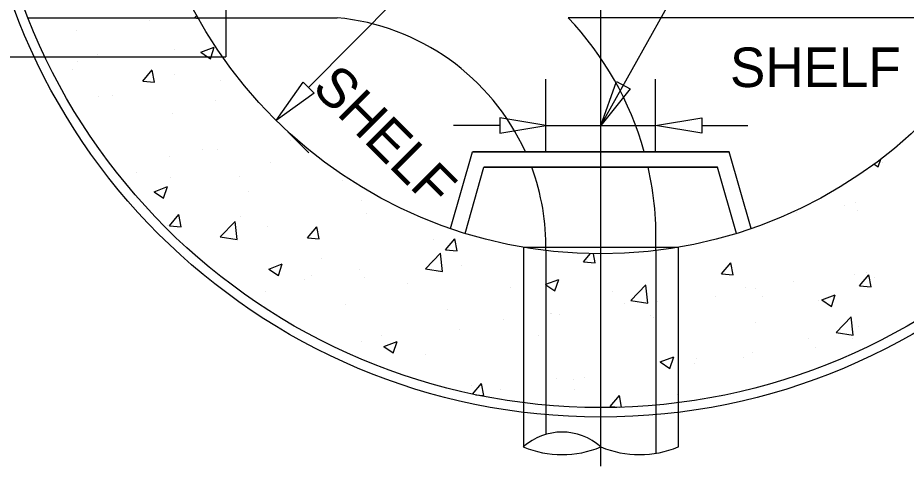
# Model space of a CAD drawing. Extents: x 6712067 to 6713867, y 1867712 to 1869162.
# Drawn here: x 6712906.2 to 6713040.8, y 1867921.4 to 1867989.4 of the extents above; entities that cross this region are included whole.
import ezdxf

# ---------------------------------------------------------------- set-up
doc = ezdxf.new("R2010")
doc.units = 0
for name, color, linetype in [('G-MARK', 7, 'Continuous'), ('G-TEXT', 7, 'Continuous'), ('Misc CnstDet(22)', 7, 'Continuous')]:
    doc.layers.add(name, color=color, linetype=linetype)

msp = doc.modelspace()

# ---------------------------------------------------------------- linework, layer by layer
at = {"layer": 'G-MARK'}
for p, q in [((6713038.81, 1868068.39), (6712950.27, 1867978.84)), ((6712979.24, 1867973.11), (6712972.24, 1867973.11)), ((6712986.22, 1867973.11), (6713002.85, 1867973.11)), ((6713009.84, 1867973.11), (6713016.84, 1867973.11))]:
    msp.add_line(p, q, dxfattribs=at)
at = {"layer": 'G-TEXT'}
for points in [[(6712949.44, 1867979.65), (6712951.11, 1867978.01), (6712945.36, 1867973.86)], [(6712998.97, 1867978.64), (6712994.54, 1867973.11), (6712996.93, 1867979.78)], [(6712979.24, 1867974.27), (6712979.24, 1867971.94), (6712986.22, 1867973.11)], [(6713009.84, 1867974.27), (6713009.84, 1867971.94), (6713002.85, 1867973.11)]]:
    msp.add_lwpolyline(points, close=True, dxfattribs=at)
at = {"layer": 'Misc CnstDet(22)'}
for p, q in [((6712994.54, 1867921.43), (6712994.54, 1868124.34)), ((6712937.71, 1868003.49), (6712937.71, 1867983.53)), ((6712907.75, 1867989.43), (6712933.49, 1867989.43)), ((6712933, 1867989.42), (6712933.01, 1867989.43)), ((6712933, 1867989.42), (6712933.55, 1867989.34)), ((6712933.01, 1867989.43), (6712933.32, 1867989.75)), ((6712933.49, 1867989.43), (6712954.61, 1867989.43)), ((6713055.59, 1867989.43), (6712989.59, 1867989.43)), ((6712926.17, 1867989), (6712926.17, 1867989)), ((6712915.13, 1867987.56), (6712915.13, 1867987.56)), ((6712918.35, 1867983.93), (6712918.35, 1867983.93)), ((6712930.02, 1867984.63), (6712930.02, 1867984.63)), ((6712933.94, 1867984.19), (6712935.99, 1867984.98)), ((6712933.94, 1867984.19), (6712934.93, 1867983.53)), ((6712935.49, 1867983.53), (6712935.99, 1867984.98)), ((6712880.72, 1867983.53), (6712908.71, 1867983.53)), ((6712908.71, 1867983.53), (6712937.71, 1867983.53)), ((6712915.29, 1867982.76), (6712915.29, 1867982.76)), ((6712934.93, 1867983.53), (6712935.39, 1867983.22)), ((6712935.39, 1867983.22), (6712935.49, 1867983.53)), ((6712914.46, 1867981.51), (6712914.46, 1867981.51)), ((6712925.16, 1867979.83), (6712926.57, 1867981.51)), ((6712926.91, 1867979.67), (6712926.56, 1867981.5)), ((6712930.02, 1867980.86), (6712930.02, 1867980.86)), ((6712936.91, 1867979.94), (6712936.91, 1867979.94)), ((6712986.22, 1867969.22), (6712986.22, 1867980.1)), ((6713002.85, 1867969.22), (6713002.85, 1867980.1)), ((6712925.16, 1867979.83), (6712926.91, 1867979.67)), ((6712918.5, 1867977.52), (6712918.5, 1867977.52)), ((6712920.61, 1867977.6), (6712920.61, 1867977.6)), ((6712936.17, 1867976.94), (6712936.17, 1867976.94)), ((6712929.67, 1867974.92), (6712929.67, 1867974.92)), ((6712945.36, 1867973.86), (6712945.36, 1867973.86)), ((6712945.36, 1867973.86), (6712945.36, 1867973.86)), ((6712947.1, 1867972.14), (6712950.33, 1867968.93)), ((6713002.85, 1867973.11), (6713002.85, 1867973.11)), ((6712947.58, 1867970.85), (6712947.58, 1867970.85)), ((6712934.14, 1867969.46), (6712934.14, 1867969.46)), ((6712936.54, 1867969.4), (6712936.54, 1867969.4)), ((6712929.24, 1867968.44), (6712929.24, 1867968.44)), ((6712971.76, 1867957.47), (6712975.08, 1867969.09)), ((6712971.76, 1867957.47), (6712975.08, 1867969.09)), ((6712975.08, 1867969.09), (6713014, 1867969.09)), ((6713014, 1867969.09), (6712975.08, 1867969.09)), ((6713017.33, 1867957.47), (6713014, 1867969.09)), ((6713017.33, 1867957.47), (6713014, 1867969.09)), ((6713036.57, 1867966.81), (6713036.96, 1867967.98)), ((6712944.45, 1867967.41), (6712944.45, 1867967.41)), ((6712973.98, 1867956.74), (6712976.84, 1867966.76)), ((6712973.98, 1867956.74), (6712976.84, 1867966.76)), ((6712976.84, 1867966.76), (6713012.24, 1867966.76)), ((6713012.24, 1867966.76), (6712976.84, 1867966.76)), ((6712986.22, 1867966.77), (6712986.22, 1867966.77)), ((6713002.85, 1867966.77), (6713002.85, 1867966.77)), ((6713015.1, 1867956.74), (6713012.24, 1867966.76)), ((6713015.1, 1867956.74), (6713012.24, 1867966.76)), ((6713035.95, 1867967.22), (6713036.57, 1867966.81)), ((6713037.25, 1867967.45), (6713037.25, 1867967.45)), ((6712924.22, 1867966.04), (6712924.22, 1867966.04)), ((6712929.32, 1867965.22), (6712929.32, 1867965.22)), ((6712939.78, 1867965.39), (6712939.78, 1867965.39)), ((6712926.85, 1867963.06), (6712928.89, 1867963.84)), ((6712928.3, 1867962.08), (6712928.89, 1867963.84)), ((6712955.35, 1867964.72), (6712955.35, 1867964.72)), ((6712926.85, 1867963.06), (6712928.3, 1867962.08)), ((6712941.13, 1867963.06), (6712941.13, 1867963.06)), ((6712958.32, 1867961.78), (6712958.32, 1867961.78)), ((6713033.14, 1867961.44), (6713033.14, 1867961.44)), ((6712959.06, 1867959.75), (6712959.06, 1867959.75)), ((6713024.14, 1867959.96), (6713024.14, 1867959.96)), ((6713031.44, 1867960.92), (6713031.44, 1867960.92)), ((6713033.4, 1867960.21), (6713033.4, 1867960.21)), ((6712929.21, 1867957.9), (6712930.61, 1867959.58)), ((6712930.95, 1867957.75), (6712930.61, 1867959.58)), ((6712936.87, 1867956.19), (6712939.14, 1867958.56)), ((6712939.46, 1867955.79), (6712939.14, 1867958.56)), ((6712939.91, 1867959.35), (6712939.91, 1867959.35)), ((6712928.87, 1867957.9), (6712928.87, 1867957.9)), ((6712929.21, 1867957.9), (6712930.95, 1867957.75)), ((6712944.1, 1867957.71), (6712944.1, 1867957.71)), ((6712950.11, 1867956.08), (6712951.52, 1867957.75)), ((6712951.86, 1867955.92), (6712951.52, 1867957.75)), ((6712936.87, 1867956.19), (6712939.46, 1867955.79)), ((6712950.11, 1867956.08), (6712951.86, 1867955.93)), ((6712969.25, 1867955.78), (6712969.25, 1867955.78)), ((6712971.02, 1867954.24), (6712972.43, 1867955.92)), ((6712972.77, 1867954.09), (6712972.43, 1867955.92)), ((6712982.81, 1867954.64), (6712982.81, 1867924.35)), ((6712982.81, 1867954.64), (6713006.28, 1867954.64)), ((6713006.28, 1867954.64), (6713006.28, 1867924.35)), ((6712967.98, 1867951.37), (6712970.25, 1867953.74)), ((6712970.57, 1867950.97), (6712970.24, 1867953.74)), ((6712971.02, 1867954.24), (6712972.77, 1867954.09)), ((6712986.23, 1867954.14), (6712986.23, 1867926.26)), ((6712991.93, 1867952.42), (6712992.97, 1867953.67)), ((6712993.67, 1867952.27), (6712993.41, 1867953.66)), ((6713002.86, 1867954.14), (6713002.86, 1867923.38)), ((6712944.25, 1867951.32), (6712946.29, 1867952.11)), ((6712945.69, 1867950.34), (6712946.29, 1867952.1)), ((6712952.26, 1867952.87), (6712952.26, 1867952.87)), ((6712968.99, 1867952.69), (6712968.99, 1867952.69)), ((6712973.43, 1867951.92), (6712973.43, 1867951.92)), ((6712991.93, 1867952.42), (6712993.67, 1867952.27)), ((6713012.84, 1867950.59), (6713014.24, 1867952.27)), ((6713014.58, 1867950.43), (6713014.24, 1867952.26)), ((6712944.25, 1867951.32), (6712945.69, 1867950.34)), ((6712950.65, 1867950.28), (6712950.65, 1867950.28)), ((6712957.95, 1867951.25), (6712957.95, 1867951.25)), ((6712967.98, 1867951.37), (6712970.57, 1867950.97)), ((6713012.84, 1867950.59), (6713014.58, 1867950.43)), ((6713033.05, 1867950.5), (6713033.05, 1867950.5)), ((6713033.75, 1867948.76), (6713035.15, 1867950.43)), ((6713034.82, 1867950.88), (6713034.82, 1867950.88)), ((6713035.48, 1867948.61), (6713035.15, 1867950.43)), ((6712949.66, 1867949.82), (6712949.66, 1867949.82)), ((6712958.71, 1867950.05), (6712958.71, 1867950.05)), ((6712965.23, 1867949.17), (6712965.23, 1867949.17)), ((6712986.14, 1867948.99), (6712986.23, 1867949.02)), ((6712986.14, 1867948.99), (6712986.23, 1867948.93)), ((6712986.23, 1867949.02), (6712988.18, 1867949.77)), ((6712986.23, 1867948.93), (6712987.59, 1867948.01)), ((6712987.59, 1867948.01), (6712988.18, 1867949.77)), ((6712999.09, 1867946.54), (6713001.35, 1867948.92)), ((6713023.78, 1867949.42), (6713023.78, 1867949.42)), ((6713036.06, 1867950.05), (6713036.06, 1867950.05)), ((6712943.74, 1867948), (6712943.74, 1867948)), ((6712980.79, 1867948.52), (6712980.79, 1867948.52)), ((6712996.35, 1867947.86), (6712996.35, 1867947.86)), ((6713001.67, 1867946.14), (6713001.35, 1867948.91)), ((6713016.48, 1867948.46), (6713016.48, 1867948.46)), ((6713017.91, 1867948.32), (6713017.91, 1867948.32)), ((6713033.75, 1867948.76), (6713035.49, 1867948.61)), ((6712999.09, 1867946.54), (6713001.67, 1867946.14)), ((6713003.19, 1867946.45), (6713003.19, 1867946.45)), ((6713011.91, 1867947.2), (6713011.91, 1867947.2)), ((6713019.05, 1867947.14), (6713019.05, 1867947.14)), ((6713027.47, 1867946.54), (6713027.47, 1867946.54)), ((6713028.03, 1867946.66), (6713030.07, 1867947.44)), ((6713028.03, 1867946.66), (6713029.48, 1867945.67)), ((6713029.48, 1867945.67), (6713030.07, 1867947.44)), ((6712955.82, 1867945.91), (6712955.82, 1867945.91)), ((6712971.38, 1867945.26), (6712971.38, 1867945.26)), ((6712998.07, 1867946.04), (6712998.07, 1867946.04)), ((6712979.73, 1867943.63), (6712979.73, 1867943.63)), ((6712986.94, 1867944.6), (6712986.94, 1867944.6)), ((6712987.03, 1867944.58), (6712987.03, 1867944.58)), ((6712988.22, 1867944.4), (6712988.22, 1867944.4)), ((6713002.05, 1867944.22), (6713002.05, 1867944.22)), ((6713002.5, 1867943.94), (6713002.5, 1867943.94)), ((6713030.19, 1867941.72), (6713032.46, 1867944.09)), ((6713032.79, 1867941.32), (6713032.46, 1867944.09)), ((6712973.08, 1867942.22), (6712973.08, 1867942.22)), ((6713018.05, 1867943.28), (6713018.05, 1867943.28)), ((6713033.61, 1867942.63), (6713033.61, 1867942.63)), ((6712961.32, 1867941.19), (6712961.32, 1867941.19)), ((6712985.06, 1867941.31), (6712985.06, 1867941.31)), ((6713030.19, 1867941.72), (6713032.79, 1867941.32)), ((6712958.35, 1867940.34), (6712958.35, 1867940.34)), ((6712961.65, 1867939.59), (6712963.69, 1867940.37)), ((6712961.65, 1867939.59), (6712963.1, 1867938.61)), ((6712963.09, 1867938.6), (6712963.69, 1867940.37)), ((6713026.04, 1867940.74), (6713026.04, 1867940.74)), ((6713032.69, 1867940.8), (6713032.69, 1867940.8)), ((6712968.05, 1867938.38), (6712968.05, 1867938.38)), ((6713017.56, 1867938.61), (6713017.56, 1867938.61)), ((6713027.14, 1867939.38), (6713027.14, 1867939.38)), ((6713003.53, 1867937.25), (6713005.58, 1867938.04)), ((6713003.53, 1867937.25), (6713004.99, 1867936.27)), ((6713004.99, 1867936.27), (6713005.58, 1867938.03)), ((6713008.81, 1867936.96), (6713008.81, 1867936.96)), ((6713009.04, 1867937.82), (6713009.04, 1867937.82)), ((6713016.1, 1867937.92), (6713016.1, 1867937.92)), ((6713002.83, 1867936.75), (6713002.83, 1867936.75)), ((6712987.87, 1867934.7), (6712987.87, 1867934.7)), ((6712990.39, 1867934.54), (6712990.39, 1867934.54)), ((6712992.03, 1867934.91), (6712992.03, 1867934.91)), ((6712974.99, 1867933.7), (6712974.99, 1867933.7)), ((6712975.12, 1867932.37), (6712976.47, 1867934)), ((6712976.81, 1867932.16), (6712976.47, 1867934)), ((6712979.35, 1867933.09), (6712979.35, 1867933.09)), ((6712990.55, 1867933.03), (6712990.55, 1867933.03)), ((6712975.58, 1867932.28), (6712976.81, 1867932.17)), ((6712995.97, 1867930.49), (6712997.38, 1867932.16)), ((6712997.7, 1867930.38), (6712997.38, 1867932.16)), ((6713006.11, 1867932.38), (6713006.11, 1867932.38)), ((6712995.97, 1867930.49), (6712997.36, 1867930.37))]:
    msp.add_line(p, q, dxfattribs=at)
msp.add_lwpolyline([(6712994.54, 1867973.11), (6713006.42, 1867994.39), (6713037.47, 1868002.61)], dxfattribs=at)
for radius in [94.73, 93.28, 69.96]:
    msp.add_circle((6712994.54, 1868023.61), radius, dxfattribs=at)
for centre, radius, start, end in [((6712951.34, 1867954.69), 34.89, 24.3848, 84.6346), ((6712954.52, 1867956.11), 48.38, 15.5784, 43.5382), ((6712951.34, 1867954.69), 34.89, 359.098, 20.2443), ((6712954.52, 1867956.11), 48.38, 357.6759, 12.7298), ((6712988.67, 1867917.86), 8.75, 47.8917, 132.1083), ((6712988.67, 1867938.54), 15.35, 247.5261, 292.4739), ((6713000.41, 1867938.54), 15.35, 247.5261, 292.4739)]:
    msp.add_arc(centre, radius, start, end, dxfattribs=at)

# ---------------------------------------------------------------- texts
msp.add_text('SHELF', height=6, dxfattribs=at).set_placement((6713014.11, 1867978.92))
msp.add_text('SHELF', height=6, rotation=315.0264, dxfattribs=at).set_placement((6712950.6, 1867978.57))

doc.saveas('drawing.dxf')
